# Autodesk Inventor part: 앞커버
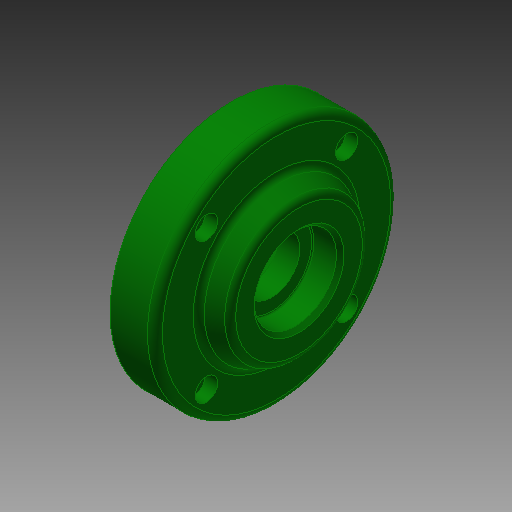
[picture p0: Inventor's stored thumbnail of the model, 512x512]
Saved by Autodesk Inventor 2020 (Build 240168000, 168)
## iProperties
Created: 2015-12
Part Number: 앞커버
Document SubType Name: Modeling
Designer: 앞커버
Density: 2.71 g/cm^3
Mass: 114.339 g
Surface Area: 117.889 cm^2
Volume: 42.1916 cm^3
Material: 알루미늄-6061
Appearance: 진녹색
Company: 한국ATC센터
Author: mdu
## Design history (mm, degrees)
sketch "스케치1"
  geometry: L1 (-11.5, 0)-(11.5, 0); L2 (11.5, 0)-(11.5, 22.5); L3 (11.5, 22.5)-(6.5, 22.5); L4 (6.5, 22.5)-(6.5, 32.5); L5 (6.5, 32.5)-(-5.5, 32.5); L6 (-5.5, 32.5)-(-5.5, 21); L7 (-5.5, 21)-(-11.5, 18.202); L8 (-11.5, 18.202)-(-11.5, 0); 2 further points
  constraints: 16 end point, 3 parallel, 3 perpendicular, 1 coincident, 1 horizontal, 1 midpoint
  dimensions: "d0" = 23 distance of L1.start L1.end; "d1" = 65 diameter of L5 L1; "d2" = 45 diameter of L3 L1; "d3" = 42 diameter of L6.end L1; "d4" = 115 deg angle of L7 L6; "d5" = 12 distance of L4.end L5.end; "d6" = 5 distance of L2.end L3.end
revolve "회전1" sketch "스케치1" stored, may be unused: angle "d7" = 90 deg
sketch "스케치2"
  geometry: L1 (0, 0)-(32.5, 0); L2 (0, 0)-(18.738, 18.738); 1 further point
  constraints: 4 end point, 1 horizontal, 1 horizontal alignment, 1 other
  dimensions: "d8" = 45 deg angle of L1 L2; "d9" = 26.5 distance of L1.start L2.end
hole "구멍1" sketch "스케치2" at (18.738, 18.738) diameter "d10" = 3.4; stored, may be unused: countersink angle "d14" = 90 deg, drill point angle "d16" = 118 deg; dims "d11" = 6, "d12" = 6, "d13" = 3.3, "d15" = 8
fillet "모깎기1" dims "d20" = 2
hole "구멍2" diameter "d23" = 15; stored, may be unused: countersink angle "d27" = 90 deg, drill point angle "d29" = 118 deg; dims "d21" = 10, "d22" = 10, "d24" = 6, "d25" = 32, "d26" = 10, "d28" = 8
hole "구멍3" diameter "d32" = 22; stored, may be unused: countersink angle "d36" = 90 deg, drill point angle "d38" = 0 deg; dims "d30" = 10, "d31" = 10, "d33" = 6, "d34" = 32, "d35" = 10, "d37" = 7.3
chamfer "모따기1" distance "d39" = 1; stored, may be unused: second distance "d40" = 2, angle "d41" = 45 deg
fillet "모깎기2" dims "d42" = 0.3
node "작업 평면1"
sketch "스케치3"
  geometry: 2 further points
  constraints: 1 coincident, 1 other
feature "엠보싱1" sketch "스케치3" dims "d20" = 2, "d44" = 0.3, "d45" = 0
fillet "모깎기3" dims "d46" = 0.2
fillet "모깎기4" dims "d47" = 0.1
node "솔리드1"
pattern_circular "원형 패턴1" dims angle "d18" = 360 deg
